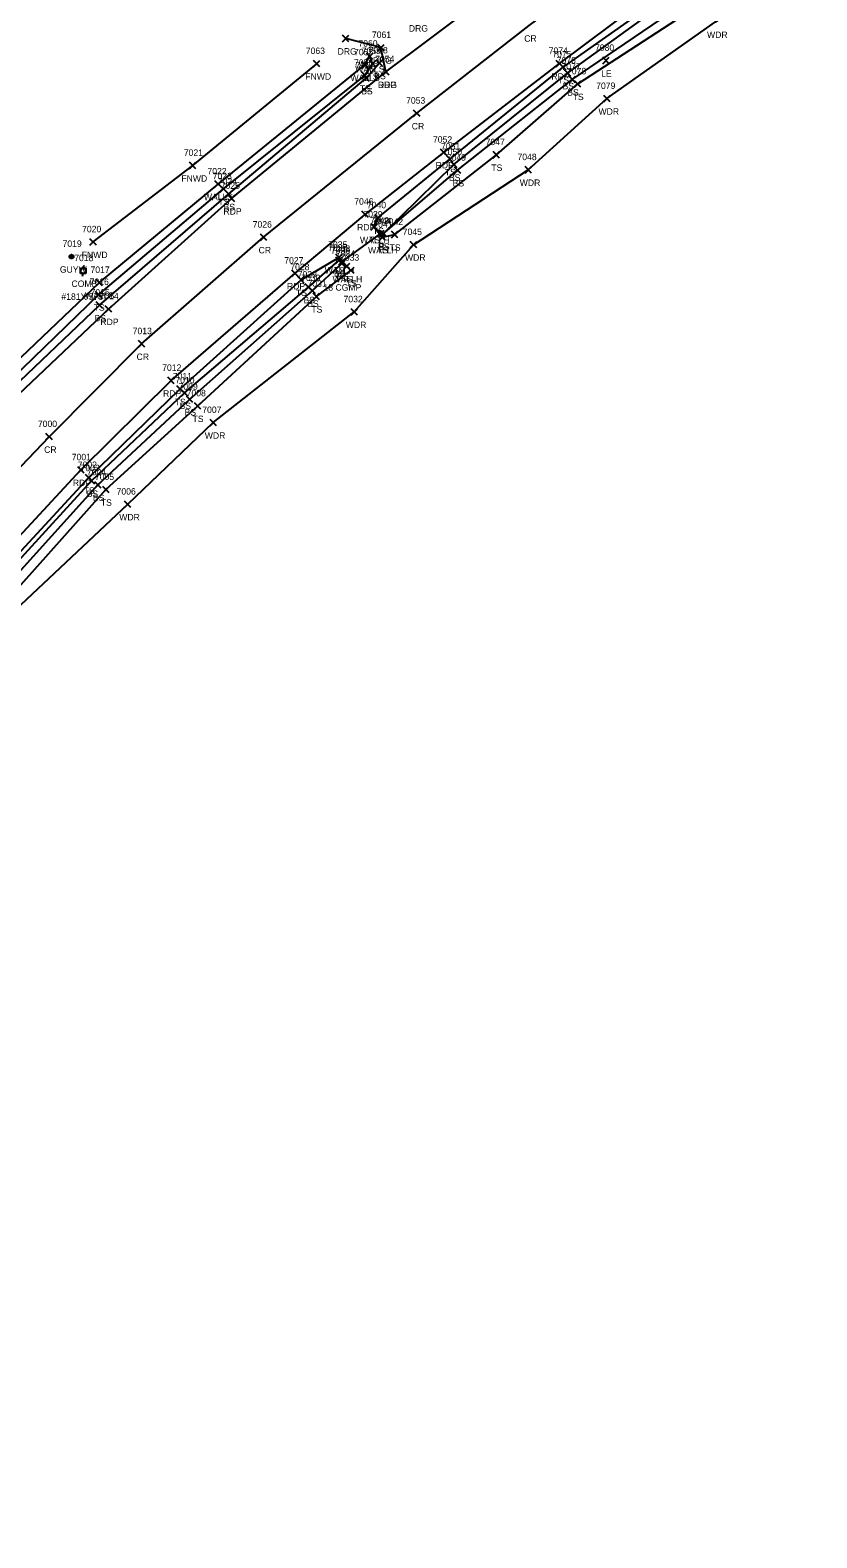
# Model space of a CAD drawing. Extents: x 1611797 to 1633212, y 298978 to 305475.
# Drawn here: x 1623974.4 to 1624218.3, y 303824.4 to 304292 of the extents above; entities that cross this region are included whole.
import ezdxf

# ---------------------------------------------------------------- set-up
doc = ezdxf.new("R2010")
doc.units = 0
for name, color, linetype in [('D_A', 7, 'Continuous'), ('D_C', 7, 'Continuous'), ('D_I', 7, 'Continuous'), ('D_TIC', 7, 'Continuous'), ('DCP', 7, 'Continuous'), ('DHW', 7, 'Continuous'), ('L_A', 7, 'Continuous'), ('L_I', 7, 'Continuous'), ('L_TIC', 7, 'Continuous'), ('LAWA', 7, 'Continuous'), ('LELB', 7, 'Continuous'), ('LFNC', 7, 'Continuous'), ('LWS', 7, 'Continuous'), ('P_A', 7, 'Continuous'), ('P_I', 7, 'Continuous'), ('P_TIC', 7, 'Continuous'), ('PET', 7, 'Continuous'), ('PRC', 7, 'Continuous'), ('R_A', 7, 'Continuous'), ('R_I', 7, 'Continuous'), ('R_TIC', 7, 'Continuous'), ('RDG', 7, 'Continuous'), ('U_A', 7, 'Continuous'), ('U_C', 7, 'Continuous'), ('U_I', 7, 'Continuous'), ('UP', 7, 'Continuous'), ('UPGW', 7, 'Continuous')]:
    doc.layers.add(name, color=color, linetype=linetype)

msp = doc.modelspace()

# ---------------------------------------------------------------- linework, layer by layer
at = {"layer": 'D_TIC'}
for points in [[(1624080.07, 304229.9), (1624082.07, 304231.9)], [(1624082.07, 304229.9), (1624080.07, 304231.9)], [(1624082.15, 304227.96), (1624084.15, 304229.96)], [(1624084.15, 304227.96), (1624082.15, 304229.96)], [(1624082.58, 304226.76), (1624084.58, 304228.76)], [(1624084.58, 304226.76), (1624082.58, 304228.76)], [(1624069.13, 304220.5), (1624071.13, 304222.5)], [(1624071.13, 304220.5), (1624069.13, 304222.5)], [(1624070.05, 304219.18), (1624072.05, 304221.18)], [(1624072.05, 304219.18), (1624070.05, 304221.18)], [(1624071.56, 304217.74), (1624073.56, 304219.74)], [(1624073.56, 304217.74), (1624071.56, 304219.74)]]:
    msp.add_lwpolyline(points, dxfattribs=at)
at = {"layer": 'DCP'}
msp.add_lwpolyline([(1624071.05, 304220.18), (1624083.15, 304228.96)], dxfattribs=at)
at = {"layer": 'DHW'}
for points in [[(1624081.07, 304230.9), (1624083.58, 304227.76)], [(1624072.56, 304218.74), (1624070.13, 304221.5)]]:
    msp.add_lwpolyline(points, dxfattribs=at)
at = {"layer": 'L_TIC'}
for points in [[(1624062.23, 304280.59), (1624064.23, 304282.59)], [(1624064.23, 304280.59), (1624062.23, 304282.59)], [(1624078.64, 304282.87), (1624080.64, 304284.87)], [(1624080.64, 304282.87), (1624078.64, 304284.87)], [(1624078.64, 304282.87), (1624080.64, 304284.87)], [(1624080.64, 304282.87), (1624078.64, 304284.87)], [(1624079.58, 304280.57), (1624081.58, 304282.57)], [(1624081.58, 304280.57), (1624079.58, 304282.57)], [(1624081.66, 304280.77), (1624083.66, 304282.77)], [(1624083.66, 304280.77), (1624081.66, 304282.77)], [(1624151.96, 304281.56), (1624153.96, 304283.56)], [(1624153.96, 304281.56), (1624151.96, 304283.56)], [(1624077.15, 304280.19), (1624079.15, 304282.19)], [(1624079.15, 304280.19), (1624077.15, 304282.19)], [(1624077.2, 304276.92), (1624079.2, 304278.92)], [(1624079.2, 304276.92), (1624077.2, 304278.92)], [(1624077.59, 304276.07), (1624079.59, 304278.07)], [(1624079.59, 304276.07), (1624077.59, 304278.07)], [(1624138.65, 304279.53), (1624140.65, 304281.53)], [(1624140.65, 304279.53), (1624138.65, 304281.53)], [(1624140.05, 304277.64), (1624142.05, 304279.64)], [(1624142.05, 304277.64), (1624140.05, 304279.64)], [(1624141.5, 304275.67), (1624143.5, 304277.67)], [(1624143.5, 304275.67), (1624141.5, 304277.67)], [(1624143.2, 304274.29), (1624145.2, 304276.29)], [(1624145.2, 304274.29), (1624143.2, 304276.29)], [(1624152.26, 304269.75), (1624154.26, 304271.75)], [(1624154.26, 304269.75), (1624152.26, 304271.75)], [(1624023.79, 304248.99), (1624025.79, 304250.99)], [(1624025.79, 304248.99), (1624023.79, 304250.99)], [(1624103.56, 304250.96), (1624105.56, 304252.96)], [(1624105.56, 304250.96), (1624103.56, 304252.96)], [(1624104.8, 304249.27), (1624106.8, 304251.27)], [(1624106.8, 304249.27), (1624104.8, 304251.27)], [(1624117.97, 304252.32), (1624119.97, 304254.32)], [(1624119.97, 304252.32), (1624117.97, 304254.32)], [(1624031.69, 304243.25), (1624033.69, 304245.25)], [(1624033.69, 304243.25), (1624031.69, 304245.25)], [(1624105.94, 304247.51), (1624107.94, 304249.51)], [(1624107.94, 304247.51), (1624105.94, 304249.51)], [(1624127.84, 304247.67), (1624129.84, 304249.67)], [(1624129.84, 304247.67), (1624127.84, 304249.67)], [(1624033.32, 304241.74), (1624035.32, 304243.74)], [(1624035.32, 304241.74), (1624033.32, 304243.74)], [(1624034.9, 304240.13), (1624036.9, 304242.13)], [(1624036.9, 304240.13), (1624034.9, 304242.13)], [(1624080.07, 304229.9), (1624082.07, 304231.9)], [(1624082.07, 304229.9), (1624080.07, 304231.9)], [(1624081.23, 304232.74), (1624083.23, 304234.74)], [(1624083.23, 304232.74), (1624081.23, 304234.74)], [(1623992.89, 304225.29), (1623994.89, 304227.29)], [(1623994.89, 304225.29), (1623992.89, 304227.29)], [(1624082.58, 304226.76), (1624084.58, 304228.76)], [(1624084.58, 304226.76), (1624082.58, 304228.76)], [(1624082.84, 304227.86), (1624084.84, 304229.86)], [(1624084.84, 304227.86), (1624082.84, 304229.86)], [(1624082.84, 304227.86), (1624084.84, 304229.86)], [(1624084.84, 304227.86), (1624082.84, 304229.86)], [(1624086.42, 304227.59), (1624088.42, 304229.59)], [(1624088.42, 304227.59), (1624086.42, 304229.59)], [(1624092.25, 304224.45), (1624094.25, 304226.45)], [(1624094.25, 304224.45), (1624092.25, 304226.45)], [(1624069.13, 304220.5), (1624071.13, 304222.5)], [(1624071.13, 304220.5), (1624069.13, 304222.5)], [(1624069.13, 304219.57), (1624071.13, 304221.57)], [(1624071.13, 304219.57), (1624069.13, 304221.57)], [(1624069.13, 304219.57), (1624071.13, 304221.57)], [(1624071.13, 304219.57), (1624069.13, 304221.57)], [(1624070.01, 304218.63), (1624072.01, 304220.63)], [(1624072.01, 304218.63), (1624070.01, 304220.63)], [(1624071.56, 304217.74), (1624073.56, 304219.74)], [(1624073.56, 304217.74), (1624071.56, 304219.74)], [(1624072.81, 304216.48), (1624074.81, 304218.48)], [(1624074.81, 304216.48), (1624072.81, 304218.48)], [(1623994.85, 304212.69), (1623996.85, 304214.69)], [(1623996.85, 304212.69), (1623994.85, 304214.69)], [(1624057.38, 304213.54), (1624059.38, 304215.54)], [(1624059.38, 304213.54), (1624057.38, 304215.54)], [(1624059.69, 304211.27), (1624061.69, 304213.27)], [(1624061.69, 304211.27), (1624059.69, 304213.27)], [(1623994.65, 304208.96), (1623996.65, 304210.96)], [(1623996.65, 304208.96), (1623994.65, 304210.96)], [(1623994.88, 304205.68), (1623996.88, 304207.68)], [(1623996.88, 304205.68), (1623994.88, 304207.68)], [(1624060.85, 304210.18), (1624062.85, 304212.18)], [(1624062.85, 304210.18), (1624060.85, 304212.18)], [(1624062.15, 304208.38), (1624064.15, 304210.38)], [(1624064.15, 304208.38), (1624062.15, 304210.38)], [(1624073.89, 304203.59), (1624075.89, 304205.59)], [(1624075.89, 304203.59), (1624073.89, 304205.59)], [(1624019.81, 304179.67), (1624021.81, 304181.67)], [(1624021.81, 304179.67), (1624019.81, 304181.67)], [(1624021.26, 304178.45), (1624023.26, 304180.45)], [(1624023.26, 304178.45), (1624021.26, 304180.45)], [(1624022.82, 304176.46), (1624024.82, 304178.46)], [(1624024.82, 304176.46), (1624022.82, 304178.46)], [(1624025.32, 304174.43), (1624027.32, 304176.43)], [(1624027.32, 304174.43), (1624025.32, 304176.43)], [(1624030.16, 304169.25), (1624032.16, 304171.25)], [(1624032.16, 304169.25), (1624030.16, 304171.25)], [(1623991.55, 304152.19), (1623993.55, 304154.19)], [(1623993.55, 304152.19), (1623991.55, 304154.19)], [(1623992.44, 304151.2), (1623994.44, 304153.2)], [(1623994.44, 304151.2), (1623992.44, 304153.2)], [(1623994.39, 304149.94), (1623996.39, 304151.94)], [(1623996.39, 304149.94), (1623994.39, 304151.94)], [(1623996.87, 304148.47), (1623998.87, 304150.47)], [(1623998.87, 304148.47), (1623996.87, 304150.47)], [(1624003.64, 304143.93), (1624005.64, 304145.93)], [(1624005.64, 304143.93), (1624003.64, 304145.93)]]:
    msp.add_lwpolyline(points, dxfattribs=at)
at = {"layer": 'LAWA'}
msp.add_lwpolyline([(1623820.79, 303877.68), (1623816.25, 303882.45), (1623845.39, 303933.13), (1623868.52, 303966.33), (1623895.88, 304001.62), (1623916.89, 304037.42), (1623938.51, 304074.19), (1623964.42, 304107.21), (1624004.64, 304144.93), (1624031.16, 304170.25), (1624074.89, 304204.59), (1624093.25, 304225.45), (1624128.84, 304248.67), (1624153.26, 304270.75), (1624186.93, 304294.55), (1624240.75, 304330.36)], dxfattribs=at)
at = {"layer": 'LELB'}
for points in [[(1624083.58, 304227.76), (1624087.42, 304228.59), (1624118.97, 304253.32), (1624144.2, 304275.29), (1624184.93, 304301.87), (1624278.34, 304363.53)], [(1624081.07, 304230.9), (1624082.23, 304233.74), (1624104.56, 304251.96), (1624139.65, 304280.53), (1624181.13, 304309.78), (1624231.77, 304345.18)], [(1624083.84, 304228.86), (1624105.8, 304250.27), (1624141.05, 304278.64), (1624181.83, 304308.22), (1624233.12, 304343.37)], [(1624083.84, 304228.86), (1624106.94, 304248.51), (1624142.5, 304276.67), (1624183.73, 304304.83), (1624234.53, 304340.54)], [(1623853.02, 304048.84), (1623871.69, 304066.45), (1623900.2, 304105.81), (1623921.89, 304135.11), (1623965.39, 304180.63), (1623995.65, 304209.96), (1624034.32, 304242.74), (1624078.2, 304277.92), (1624080.58, 304281.57), (1624079.64, 304283.87)], [(1623859.31, 304049.34), (1623873.48, 304065.52), (1623902.17, 304104.9), (1623923.22, 304132.47), (1623966.86, 304179.03), (1623995.88, 304206.68), (1624035.9, 304241.13), (1624078.59, 304277.07), (1624082.66, 304281.77)], [(1623740.23, 303740.54), (1623735.95, 303738.13), (1623733.04, 303738.73), (1623730.26, 303741.26), (1623736.66, 303755.3), (1623756.47, 303795.98), (1623775.32, 303833.05), (1623795.61, 303873.89), (1623811.07, 303903.3), (1623831.07, 303937.59), (1623850.6, 303969.47), (1623881.4, 304014.8), (1623901.24, 304044.35), (1623930, 304082.68), (1623952.95, 304110.39), (1623992.55, 304153.19), (1624020.81, 304180.67), (1624058.38, 304214.54), (1624070.13, 304221.5)], [(1623733.78, 303740.47), (1623738.51, 303754.96), (1623759.12, 303794.85), (1623777.54, 303832.17), (1623797.8, 303872.86), (1623812.76, 303901.96), (1623832.53, 303936.61), (1623852.45, 303968.82), (1623883.01, 304013.7), (1623903, 304043.14), (1623931.54, 304080.8), (1623954.14, 304109.34), (1623993.44, 304152.2), (1624022.26, 304179.45), (1624060.69, 304212.27), (1624070.13, 304220.57)], [(1623733.78, 303740.47), (1623735.41, 303740.12), (1623741.31, 303753.52), (1623763.42, 303793.2), (1623780.16, 303829.64), (1623800.51, 303871.51), (1623815.19, 303900), (1623835, 303935.42), (1623854.96, 303967.29), (1623885.08, 304011.89), (1623905.91, 304041.32), (1623933.42, 304079.65), (1623956.31, 304107.74), (1623995.39, 304150.94), (1624023.82, 304177.46), (1624061.85, 304211.18), (1624071.01, 304219.63), (1624070.13, 304220.57)], [(1623840.63, 303933.04), (1623857.36, 303966.24), (1623887.8, 304009.35), (1623908, 304039.91), (1623936.29, 304076.6), (1623958.73, 304105.76), (1623997.87, 304149.47), (1624026.32, 304175.43), (1624063.15, 304209.38), (1624073.81, 304217.48), (1624072.56, 304218.74)]]:
    msp.add_lwpolyline(points, dxfattribs=at)
at = {"layer": 'LFNC'}
msp.add_lwpolyline([(1623993.89, 304226.29), (1624024.79, 304249.99), (1624063.23, 304281.59)], dxfattribs=at)
at = {"layer": 'LWS'}
msp.add_lwpolyline([(1623853.02, 304048.84), (1623868.94, 304068.24), (1623897.29, 304106.41), (1623918.45, 304135.75), (1623962.64, 304182.22), (1623995.85, 304213.69), (1624032.69, 304244.25), (1624078.15, 304281.19), (1624079.64, 304283.87)], dxfattribs=at)
at = {"layer": 'P_TIC'}
for points in [[(1624137.53, 304280.62), (1624139.53, 304282.62)], [(1624139.53, 304280.62), (1624137.53, 304282.62)], [(1624083.71, 304278.03), (1624085.71, 304280.03)], [(1624085.71, 304278.03), (1624083.71, 304280.03)], [(1624093.29, 304265.19), (1624095.29, 304267.19)], [(1624095.29, 304265.19), (1624093.29, 304267.19)], [(1624101.63, 304253.08), (1624103.63, 304255.08)], [(1624103.63, 304253.08), (1624101.63, 304255.08)], [(1624035.82, 304238.77), (1624037.82, 304240.77)], [(1624037.82, 304238.77), (1624035.82, 304240.77)], [(1624077.27, 304233.86), (1624079.27, 304235.86)], [(1624079.27, 304233.86), (1624077.27, 304235.86)], [(1624045.78, 304226.75), (1624047.78, 304228.75)], [(1624047.78, 304226.75), (1624045.78, 304228.75)], [(1624055.52, 304215.58), (1624057.52, 304217.58)], [(1624057.52, 304215.58), (1624055.52, 304217.58)], [(1623997.66, 304204.49), (1623999.66, 304206.49)], [(1623999.66, 304204.49), (1623997.66, 304206.49)], [(1624007.94, 304193.69), (1624009.94, 304195.69)], [(1624009.94, 304193.69), (1624007.94, 304195.69)], [(1624017.08, 304182.31), (1624019.08, 304184.31)], [(1624019.08, 304182.31), (1624017.08, 304184.31)], [(1623979.27, 304164.88), (1623981.27, 304166.88)], [(1623981.27, 304164.88), (1623979.27, 304166.88)], [(1623989.12, 304154.59), (1623991.12, 304156.59)], [(1623991.12, 304154.59), (1623989.12, 304156.59)]]:
    msp.add_lwpolyline(points, dxfattribs=at)
at = {"layer": 'PET'}
for points in [[(1623734.72, 303818.72), (1623741.35, 303832.79), (1623751.88, 303855.21), (1623768.06, 303888.23), (1623783.81, 303919.21), (1623803.8, 303953.17), (1623823.4, 303986.78), (1623844.63, 304021.43), (1623861.98, 304047.29), (1623874.41, 304064.9), (1623903.88, 304103.57), (1623926.42, 304130.92), (1623968.84, 304177.26), (1623998.66, 304205.49), (1624036.82, 304239.77), (1624084.71, 304279.03), (1624112.56, 304299.92), (1624120.23, 304305.61), (1624165.06, 304338.25), (1624214.6, 304372.95), (1624258.69, 304401.17)], [(1623753.98, 303796.37), (1623772.12, 303834.51), (1623792.43, 303875.75), (1623808.26, 303904.51), (1623828.44, 303938.4), (1623847.99, 303970.88), (1623878.6, 304016.89), (1623898.4, 304046.12), (1623927.58, 304084.75), (1623950.31, 304112.67), (1623990.12, 304155.59), (1624018.08, 304183.31), (1624056.52, 304216.58), (1624078.27, 304234.86), (1624102.63, 304254.08), (1624138.53, 304281.62), (1624179.36, 304312.24), (1624229.96, 304347.62)]]:
    msp.add_lwpolyline(points, dxfattribs=at)
at = {"layer": 'PRC'}
msp.add_lwpolyline([(1623741.55, 303802.02), (1623760.52, 303841.05), (1623780.51, 303881.51), (1623815.97, 303945.98), (1623835.49, 303978.53), (1623866.25, 304025.48), (1623886.62, 304054.99), (1623916.18, 304093.56), (1623939.04, 304122.75), (1623980.27, 304165.88), (1624008.94, 304194.69), (1624046.78, 304227.75), (1624094.29, 304266.19), (1624129.15, 304293.39), (1624172.24, 304325.39), (1624222.29, 304360.15)], dxfattribs=at)
at = {"layer": 'R_TIC'}
for points in [[(1624071.22, 304288.4), (1624073.22, 304290.4)], [(1624073.22, 304288.4), (1624071.22, 304290.4)], [(1624082.16, 304285.57), (1624084.16, 304287.57)], [(1624084.16, 304285.57), (1624082.16, 304287.57)], [(1624083.71, 304278.03), (1624085.71, 304280.03)], [(1624085.71, 304278.03), (1624083.71, 304280.03)]]:
    msp.add_lwpolyline(points, dxfattribs=at)
at = {"layer": 'RDG'}
msp.add_lwpolyline([(1624084.71, 304279.03), (1624083.16, 304286.57), (1624072.22, 304289.4)], dxfattribs=at)
at = {"layer": 'UP'}
for p, q in [((1623989.97, 304216.51), (1623989.97, 304218.17)), ((1623989.97, 304218.17), (1623991.64, 304218.17)), ((1623991.05, 304219.01), (1623990.8, 304218.17)), ((1623990.8, 304217.34), (1623990.8, 304217.34)), ((1623991.64, 304218.17), (1623991.64, 304216.51)), ((1623991.64, 304216.51), (1623989.97, 304216.51)), ((1623990.55, 304215.67), (1623990.8, 304216.51))]:
    msp.add_line(p, q, dxfattribs=at)
msp.add_circle((1623990.8, 304217.34), 0.833, dxfattribs=at)
at = {"layer": 'UPGW'}
for radius in [0.625, 0.0833]:
    msp.add_circle((1623987.19, 304221.76), radius, dxfattribs=at)

# ---------------------------------------------------------------- texts
at = {"layer": 'D_A'}
for s, p in [('WALLH', (1624076.66, 304225.9)), ('WALLH', (1624079.17, 304222.76)), ('P', (1624082.53, 304223.96)), ('WALLH', (1624065.72, 304216.5)), ('P', (1624070.42, 304215.18)), ('WALLH', (1624068.15, 304213.74))]:
    msp.add_text(s, height=2, dxfattribs=at).set_placement(p)
at = {"layer": 'D_C'}
msp.add_text('18 CGMP', height=2, dxfattribs=at).set_placement((1624065.34, 304211.18))
at = {"layer": 'D_I'}
for s, p in [('7039', (1624077.72, 304233.9)), ('7043', (1624079.81, 304231.96)), ('7041', (1624080.8, 304230.76)), ('7035', (1624066.79, 304224.5)), ('7038', (1624067.71, 304223.18)), ('7034', (1624069.23, 304221.74))]:
    msp.add_text(s, height=2, dxfattribs=at).set_placement(p)
at = {"layer": 'L_A'}
for s, p in [('WDR', (1624184.29, 304289.55)), ('FNWD', (1624059.7, 304276.59)), ('WALLS', (1624073.7, 304276.19)), ('WALLS', (1624075.19, 304278.87)), ('TS', (1624078.05, 304278.87)), ('TS', (1624078.99, 304276.57)), ('BS', (1624081.1, 304276.77)), ('LE', (1624151.45, 304277.56)), ('TS', (1624076.61, 304272.92)), ('BS', (1624077.03, 304272.07)), ('TS', (1624138.06, 304275.53)), ('BS', (1624139.49, 304273.64)), ('BS', (1624140.94, 304271.67)), ('TS', (1624142.61, 304270.29)), ('WDR', (1624150.62, 304265.75)), ('TS', (1624117.38, 304248.32)), ('FNWD', (1624021.26, 304244.99)), ('TS', (1624102.97, 304246.96)), ('BS', (1624104.24, 304245.27)), ('BS', (1624105.38, 304243.51)), ('WDR', (1624126.2, 304243.67)), ('WALLS', (1624028.24, 304239.25)), ('TS', (1624032.73, 304237.74)), ('BS', (1624034.34, 304236.13)), ('TS', (1624079.47, 304225.9)), ('TS', (1624080.64, 304228.74)), ('FNWD', (1623990.36, 304221.29)), ('TS', (1624081.99, 304222.76)), ('BS', (1624082.28, 304223.86)), ('BS', (1624082.28, 304223.86)), ('TS', (1624085.83, 304223.59)), ('WDR', (1624090.61, 304220.45)), ('TS', (1624068.54, 304216.5)), ('BS', (1624068.57, 304215.57)), ('BS', (1624068.57, 304215.57)), ('BS', (1624069.45, 304214.63)), ('TS', (1624070.97, 304213.74)), ('TS', (1624072.22, 304212.48)), ('WALLS', (1623991.39, 304208.69)), ('TS', (1624056.79, 304209.54)), ('BS', (1624059.13, 304207.27)), ('BS', (1624060.29, 304206.18)), ('TS', (1623994.06, 304204.96)), ('BS', (1623994.32, 304201.68)), ('TS', (1624061.56, 304204.38)), ('WDR', (1624072.25, 304199.59)), ('TS', (1624019.22, 304175.67)), ('BS', (1624020.7, 304174.45)), ('BS', (1624022.26, 304172.46)), ('TS', (1624024.73, 304170.43)), ('WDR', (1624028.52, 304165.25)), ('TS', (1623990.96, 304148.19)), ('BS', (1623991.88, 304147.2)), ('BS', (1623993.83, 304145.94)), ('TS', (1623996.28, 304144.47)), ('WDR', (1624002, 304139.93))]:
    msp.add_text(s, height=2, dxfattribs=at).set_placement(p)
at = {"layer": 'L_I'}
for s, p in [('7060', (1624076.17, 304286.87)), ('7060', (1624076.17, 304286.87)), ('7080', (1624149.54, 304285.56)), ('7063', (1624059.85, 304284.59)), ('7055', (1624074.82, 304284.19)), ('7056', (1624074.81, 304280.92)), ('7059', (1624077.23, 304284.57)), ('7058', (1624079.32, 304284.77)), ('7075', (1624136.31, 304283.53)), ('7076', (1624137.66, 304281.64)), ('7057', (1624075.25, 304280.07)), ('7077', (1624139.16, 304279.67)), ('7078', (1624140.86, 304278.29)), ('7079', (1624149.91, 304273.75)), ('7021', (1624022.02, 304252.99)), ('7051', (1624101.79, 304254.96)), ('7050', (1624102.37, 304253.27)), ('7047', (1624115.63, 304256.32)), ('7049', (1624103.59, 304251.51)), ('7048', (1624125.5, 304251.67)), ('7022', (1624029.35, 304247.25)), ('7023', (1624030.98, 304245.74)), ('7024', (1624032.56, 304244.13)), ('7039', (1624077.72, 304233.9)), ('7040', (1624078.81, 304236.74)), ('7020', (1623990.47, 304229.29)), ('7044', (1624080.5, 304231.86)), ('7044', (1624080.5, 304231.86)), ('7041', (1624080.8, 304230.76)), ('7042', (1624084.08, 304231.59)), ('7035', (1624066.79, 304224.5)), ('7045', (1624089.91, 304228.45)), ('7037', (1624066.79, 304223.57)), ('7037', (1624066.79, 304223.57)), ('7036', (1624067.62, 304222.63)), ('7034', (1624069.23, 304221.74)), ('7033', (1624070.47, 304220.48)), ('7017', (1623993.08, 304216.69)), ('7028', (1624055.04, 304217.54)), ('7029', (1624057.34, 304215.27)), ('7016', (1623992.82, 304212.96)), ('7030', (1624058.42, 304214.18)), ('7031', (1624060.38, 304212.38)), ('7015', (1623993.1, 304209.68)), ('7032', (1624071.55, 304207.59)), ('7011', (1624018.6, 304183.67)), ('7010', (1624019.4, 304182.45)), ('7009', (1624020.39, 304180.46)), ('7008', (1624022.9, 304178.43)), ('7007', (1624027.74, 304173.25)), ('7002', (1623989.13, 304156.19)), ('7003', (1623990.02, 304155.2)), ('7004', (1623991.97, 304153.94)), ('7005', (1623994.45, 304152.47)), ('7006', (1624001.17, 304147.93))]:
    msp.add_text(s, height=2, dxfattribs=at).set_placement(p)
at = {"layer": 'P_A'}
for s, p in [('CR', (1624127.59, 304288.39)), ('RDP', (1624136.02, 304276.62)), ('RDP', (1624082.2, 304274.03)), ('CR', (1624092.72, 304261.19)), ('RDP', (1624100.11, 304249.08)), ('RDP', (1624034.31, 304234.77)), ('RDP', (1624075.76, 304229.86)), ('CR', (1624045.21, 304222.75)), ('RDP', (1624054, 304211.58)), ('RDP', (1623996.15, 304200.49)), ('CR', (1624007.37, 304189.69)), ('RDP', (1624015.57, 304178.31)), ('CR', (1623978.7, 304160.88)), ('RDP', (1623987.61, 304150.59))]:
    msp.add_text(s, height=2, dxfattribs=at).set_placement(p)
at = {"layer": 'P_I'}
for s, p in [('7054', (1624081.37, 304282.03)), ('7074', (1624135.19, 304284.62)), ('7053', (1624090.95, 304269.19)), ('7052', (1624099.29, 304257.08)), ('7025', (1624033.48, 304242.77)), ('7046', (1624074.88, 304237.86)), ('7026', (1624043.39, 304230.75)), ('7027', (1624053.18, 304219.58)), ('7014', (1623995.89, 304208.49)), ('7013', (1624006.16, 304197.69)), ('7012', (1624015.31, 304186.31)), ('7000', (1623976.76, 304168.88)), ('7001', (1623987.27, 304158.59))]:
    msp.add_text(s, height=2, dxfattribs=at).set_placement(p)
at = {"layer": 'R_A'}
for p in [(1624091.81, 304291.54), (1624069.71, 304284.4), (1624080.65, 304281.57), (1624082.2, 304274.03)]:
    msp.add_text('DRG', height=2, dxfattribs=at).set_placement(p)
at = {"layer": 'R_I'}
for s, p in [('7061', (1624080.35, 304289.57)), ('7054', (1624081.37, 304282.03))]:
    msp.add_text(s, height=2, dxfattribs=at).set_placement(p)
at = {"layer": 'U_A'}
for s, p in [('GUYW', (1623983.58, 304216.76)), ('COMB', (1623987.19, 304212.34))]:
    msp.add_text(s, height=2, dxfattribs=at).set_placement(p)
at = {"layer": 'U_C'}
msp.add_text('#181X/575', height=2, dxfattribs=at).set_placement((1623984.05, 304208.34))
at = {"layer": 'U_I'}
for s, p in [('7019', (1623984.41, 304224.76)), ('7018', (1623988.03, 304220.34))]:
    msp.add_text(s, height=2, dxfattribs=at).set_placement(p)

doc.saveas('drawing.dxf')
